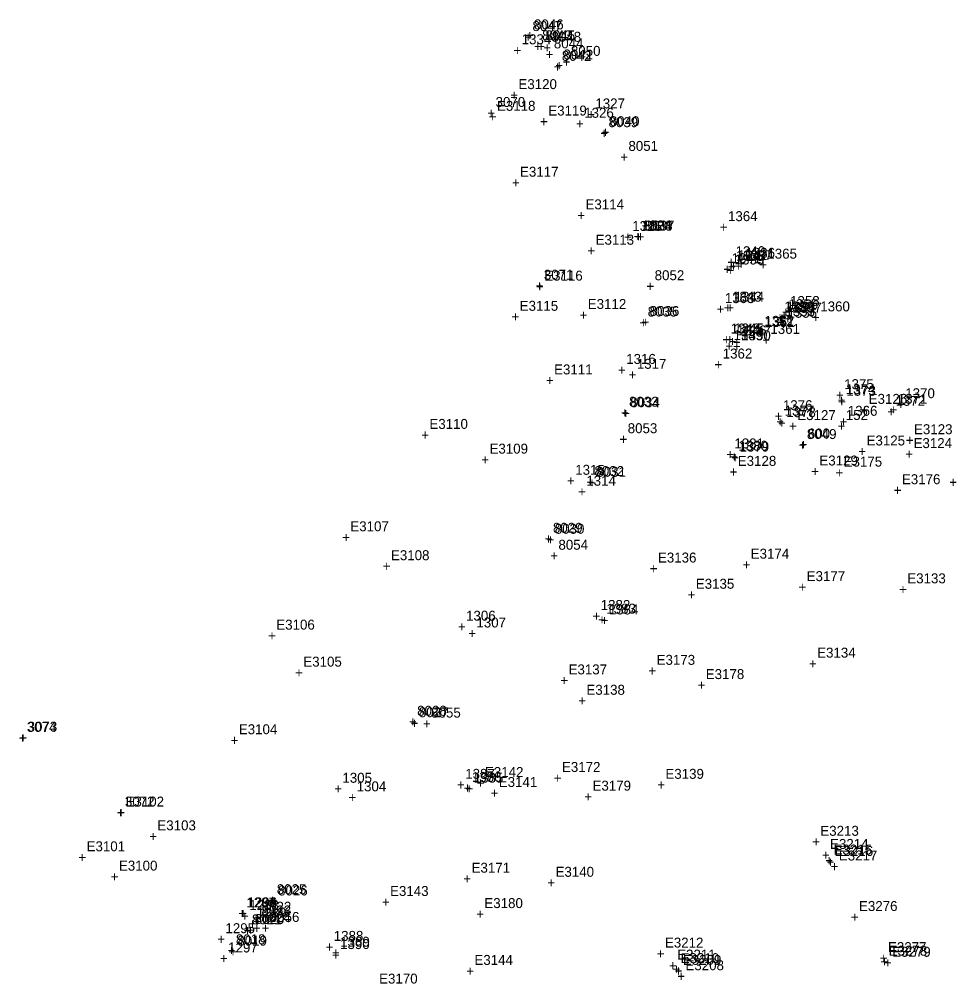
# Model space of a CAD drawing. Extents: x 1667192 to 1669644, y 336680 to 339991.
# Drawn here: x 1668101.3 to 1668335.8, y 339404.1 to 339646.3 of the extents above; entities that cross this region are included whole.
import ezdxf

# ---------------------------------------------------------------- set-up
doc = ezdxf.new("R2010")
doc.units = 0
for name, color, linetype in [('S_Control_BenchMark_Temp', 7, 'Continuous'), ('S_Control_Temp_Traverse', 7, 'Continuous'), ('S_Curb_Type_1', 7, 'Continuous'), ('S_Curb_Type_5', 7, 'Continuous'), ('S_Drainage_CB', 7, 'Continuous'), ('S_Drainage_Culvert_Top', 7, 'Continuous'), ('S_Drainage_Invert', 7, 'Continuous'), ('S_Fencing_ChainLink', 7, 'Continuous'), ('S_Fencing_Page', 7, 'Continuous'), ('S_Ground_Elevation', 7, 'Continuous'), ('S_Guardrail_Beam', 7, 'Continuous'), ('S_Roadway_Edge_Pavement', 7, 'Continuous'), ('S_Roadway_Edge_TW', 7, 'Continuous'), ('S_Traffic_Sign_SinglePost', 7, 'Continuous'), ('S_Utilities_Pole_Power', 7, 'Continuous')]:
    doc.layers.add(name, color=color, linetype=linetype)

msp = doc.modelspace()

# ---------------------------------------------------------------- texts
at = {"layer": 'S_Control_BenchMark_Temp'}
for s, p in [('8049', (1668299.17, 339540.9)), ('+', (1668297.11, 339538.15))]:
    msp.add_text(s, height=2.5, dxfattribs=at).set_placement(p)
at = {"layer": 'S_Control_Temp_Traverse'}
for s, p in [('152', (1668308.94, 339545.7)), ('+', (1668306.88, 339542.95)), ('600', (1668299.4, 339541.04)), ('600', (1668299.4, 339541.04)), ('600', (1668299.4, 339541.04)), ('600', (1668299.4, 339541.04)), ('+', (1668297.34, 339538.29)), ('+', (1668297.34, 339538.29)), ('+', (1668297.34, 339538.29)), ('+', (1668297.34, 339538.29))]:
    msp.add_text(s, height=2.5, dxfattribs=at).set_placement(p)
at = {"layer": 'S_Curb_Type_1'}
for s, p in [('8047', (1668230.24, 339643.36)), ('8043', (1668232.65, 339641.04)), ('+', (1668228.17, 339640.61)), ('+', (1668230.59, 339638.29)), ('8042', (1668237.62, 339635.88)), ('+', (1668235.56, 339633.13)), ('8039', (1668249.34, 339619.22)), ('+', (1668247.28, 339616.47)), ('8038', (1668257.99, 339593.25)), ('+', (1668255.93, 339590.5)), ('8035', (1668259.18, 339571.66)), ('+', (1668257.11, 339568.91)), ('1373', (1668309.06, 339551.77)), ('8033', (1668254.5, 339549.03)), ('+', (1668307, 339549.02)), ('1372', (1668321.43, 339549.25)), ('1378', (1668293.97, 339546.4)), ('+', (1668252.44, 339546.28)), ('+', (1668319.37, 339546.5)), ('+', (1668291.91, 339543.65)), ('1379', (1668282.24, 339537.76)), ('+', (1668280.18, 339535.01)), ('8032', (1668245.81, 339531.61)), ('+', (1668243.75, 339528.86)), ('8029', (1668235.37, 339517.35)), ('+', (1668233.31, 339514.6)), ('1384', (1668249.42, 339496.85)), ('+', (1668247.35, 339494.1)), ('8028', (1668201.27, 339471.41)), ('+', (1668199.21, 339468.66)), ('1385', (1668215.46, 339454.6)), ('+', (1668213.39, 339451.85)), ('E3215', (1668305.86, 339436.56)), ('+', (1668303.79, 339433.81)), ('8025', (1668166.01, 339426.6)), ('+', (1668163.94, 339423.85)), ('8022', (1668162.22, 339422.19)), ('8021', (1668159.77, 339419.02)), ('+', (1668160.16, 339419.44)), ('+', (1668157.71, 339416.27)), ('8018', (1668155.74, 339414.02)), ('+', (1668153.68, 339411.27)), ('1390', (1668181.91, 339412.82)), ('+', (1668179.85, 339410.07)), ('E3210', (1668267.47, 339409.28)), ('+', (1668265.41, 339406.53))]:
    msp.add_text(s, height=2.5, dxfattribs=at).set_placement(p)
at = {"layer": 'S_Curb_Type_5'}
for s, p in [('1338', (1668281.36, 339585.7)), ('1337', (1668283.03, 339585.83)), ('+', (1668279.3, 339582.95)), ('+', (1668280.97, 339583.08)), ('1339', (1668281.02, 339584.74)), ('+', (1668278.96, 339581.99)), ('1344', (1668280.99, 339575.38)), ('1354', (1668294.03, 339572.82)), ('1355', (1668294.55, 339573.52)), ('+', (1668278.93, 339572.63)), ('1353', (1668293.77, 339571.75)), ('1352', (1668288.51, 339569.33)), ('+', (1668291.7, 339569)), ('+', (1668291.97, 339570.07)), ('+', (1668292.49, 339570.77)), ('1345', (1668280.91, 339567.42)), ('1346', (1668281.59, 339566.94)), ('1347', (1668282.63, 339566.73)), ('+', (1668286.44, 339566.58)), ('+', (1668278.85, 339564.67)), ('+', (1668279.53, 339564.19)), ('+', (1668280.57, 339563.98)), ('E3279', (1668320.59, 339410.88)), ('+', (1668318.53, 339408.13))]:
    msp.add_text(s, height=2.5, dxfattribs=at).set_placement(p)
at = {"layer": 'S_Drainage_CB'}
for s, p in [('8048', (1668235.02, 339640.67)), ('+', (1668232.96, 339637.92)), ('8024', (1668162.1, 339419.57)), ('+', (1668160.04, 339416.82))]:
    msp.add_text(s, height=2.5, dxfattribs=at).set_placement(p)
at = {"layer": 'S_Drainage_Culvert_Top'}
for s, p in [('1288', (1668159.07, 339422.61)), ('1289', (1668160.97, 339420.71)), ('+', (1668157.01, 339419.86)), ('+', (1668158.91, 339417.96))]:
    msp.add_text(s, height=2.5, dxfattribs=at).set_placement(p)
at = {"layer": 'S_Drainage_Invert'}
for s, p in [('1287', (1668158.39, 339423.26)), ('+', (1668156.33, 339420.51))]:
    msp.add_text(s, height=2.5, dxfattribs=at).set_placement(p)
at = {"layer": 'S_Fencing_ChainLink'}
for s, p in [('3070', (1668220.97, 339624.29)), ('+', (1668218.91, 339621.54)), ('3071', (1668233.09, 339580.91)), ('+', (1668231.03, 339578.16)), ('3073', (1668103.42, 339467.43)), ('+', (1668101.36, 339464.68)), ('3072', (1668127.86, 339448.6)), ('+', (1668125.8, 339445.85))]:
    msp.add_text(s, height=2.5, dxfattribs=at).set_placement(p)
at = {"layer": 'S_Fencing_Page'}
for s, p in [('3074', (1668103.23, 339467.35)), ('+', (1668101.16, 339464.6))]:
    msp.add_text(s, height=2.5, dxfattribs=at).set_placement(p)
at = {"layer": 'S_Ground_Elevation'}
for s, p in [('1334', (1668227.52, 339640.05)), ('+', (1668225.46, 339637.3)), ('E3120', (1668226.71, 339628.78)), ('+', (1668224.65, 339626.03)), ('1327', (1668246.03, 339623.93)), ('E3118', (1668221.32, 339623.33)), ('E3119', (1668234.21, 339622.15)), ('1326', (1668243.23, 339621.58)), ('+', (1668219.26, 339620.58)), ('+', (1668232.15, 339619.4)), ('+', (1668243.97, 339621.18)), ('+', (1668241.17, 339618.83)), ('E3117', (1668227.12, 339606.78)), ('+', (1668225.06, 339604.03)), ('E3114', (1668243.56, 339598.59)), ('+', (1668241.5, 339595.84)), ('1325', (1668255.3, 339593.16)), ('1324', (1668257.75, 339593.29)), ('+', (1668253.24, 339590.41)), ('+', (1668255.69, 339590.54)), ('E3113', (1668246.1, 339589.7)), ('+', (1668244.04, 339586.95)), ('E3116', (1668233.19, 339580.69)), ('+', (1668231.13, 339577.94)), ('E3115', (1668227.03, 339573.11)), ('E3112', (1668244.13, 339573.57)), ('+', (1668242.07, 339570.82)), ('+', (1668224.97, 339570.36)), ('1316', (1668253.78, 339559.77)), ('1317', (1668256.45, 339558.54)), ('E3111', (1668235.67, 339557.13)), ('+', (1668251.72, 339557.02)), ('+', (1668233.61, 339554.38)), ('+', (1668254.39, 339555.79)), ('E3126', (1668314.7, 339549.74)), ('+', (1668312.64, 339546.99)), ('E3127', (1668296.76, 339545.66)), ('E3110', (1668204.35, 339543.45)), ('+', (1668294.69, 339542.91)), ('E3123', (1668326.08, 339542.12)), ('+', (1668202.29, 339540.7)), ('+', (1668324.02, 339539.37)), ('E3109', (1668219.45, 339537.24)), ('+', (1668217.39, 339534.49)), ('E3128', (1668281.81, 339534.17)), ('1315', (1668240.98, 339531.92)), ('E3175', (1668308.41, 339533.98)), ('+', (1668279.75, 339531.42)), ('+', (1668306.34, 339531.23)), ('E3176', (1668323.04, 339529.56)), ('+', (1668238.92, 339529.17)), ('1314', (1668243.76, 339529.18)), ('+', (1668334.92, 339528.82)), ('+', (1668241.7, 339526.43)), ('+', (1668320.98, 339526.81)), ('E3107', (1668184.49, 339517.74)), ('+', (1668182.43, 339514.99)), ('E3108', (1668194.7, 339510.48)), ('E3136', (1668261.76, 339509.89)), ('E3174', (1668285.06, 339510.86)), ('+', (1668283, 339508.11)), ('+', (1668192.64, 339507.73)), ('+', (1668259.7, 339507.14)), ('E3177', (1668299.12, 339505.22)), ('E3133', (1668324.39, 339504.67)), ('+', (1668297.05, 339502.47)), ('+', (1668322.33, 339501.92)), ('E3106', (1668165.89, 339493.04)), ('1306', (1668213.56, 339495.28)), ('1307', (1668216.15, 339493.58)), ('+', (1668211.5, 339492.53)), ('+', (1668163.83, 339490.29)), ('+', (1668214.09, 339490.83)), ('E3134', (1668301.75, 339486.01)), ('E3105', (1668172.68, 339483.75)), ('E3173', (1668261.42, 339484.2)), ('E3137', (1668239.31, 339481.8)), ('+', (1668259.36, 339481.45)), ('+', (1668299.69, 339483.26)), ('+', (1668170.61, 339481)), ('+', (1668237.25, 339479.05)), ('E3178', (1668273.77, 339480.62)), ('+', (1668271.71, 339477.87)), ('E3104', (1668156.48, 339466.77)), ('+', (1668154.42, 339464.02)), ('E3172', (1668237.65, 339457.3)), ('1305', (1668182.49, 339454.58)), ('E3142', (1668218.3, 339456.03)), ('E3139', (1668263.63, 339455.57)), ('1304', (1668186.07, 339452.43)), ('+', (1668216.24, 339453.28)), ('+', (1668235.59, 339454.55)), ('E3179', (1668245.32, 339452.6)), ('+', (1668261.57, 339452.82)), ('+', (1668180.43, 339451.83)), ('+', (1668243.26, 339449.85)), ('E3102', (1668128.02, 339448.61)), ('+', (1668184.01, 339449.68)), ('+', (1668125.96, 339445.86)), ('E3103', (1668136.02, 339442.64)), ('E3213', (1668302.55, 339441.26)), ('E3101', (1668118.24, 339437.38)), ('+', (1668133.96, 339439.89)), ('+', (1668300.49, 339438.51)), ('E3214', (1668304.99, 339437.97)), ('+', (1668302.93, 339435.22)), ('+', (1668116.18, 339434.63)), ('E3100', (1668126.36, 339432.52)), ('E3171', (1668214.94, 339431.99)), ('E3140', (1668236.03, 339430.97)), ('+', (1668124.3, 339429.77)), ('+', (1668212.88, 339429.24)), ('+', (1668233.97, 339428.22)), ('E3143', (1668194.47, 339426.15)), ('1296', (1668158.64, 339423.3)), ('+', (1668192.41, 339423.4)), ('E3180', (1668218.16, 339423.11)), ('+', (1668156.58, 339420.55)), ('+', (1668216.1, 339420.36)), ('1295', (1668153.11, 339416.81)), ('+', (1668151.04, 339414.06)), ('E3212', (1668263.51, 339413.19)), ('1297', (1668153.79, 339411.97)), ('+', (1668151.73, 339409.22)), ('E3144', (1668215.66, 339408.84)), ('+', (1668261.45, 339410.44)), ('E3211', (1668266.59, 339410.18)), ('+', (1668264.53, 339407.43)), ('E3170', (1668191.72, 339404.15)), ('+', (1668213.6, 339406.09))]:
    msp.add_text(s, height=2.5, dxfattribs=at).set_placement(p)
at = {"layer": 'S_Guardrail_Beam'}
for s, p in [('E3125', (1668314.16, 339539.29)), ('E3124', (1668325.96, 339538.63)), ('E3129', (1668302.31, 339534.26)), ('+', (1668312.1, 339536.54)), ('+', (1668323.9, 339535.88)), ('+', (1668300.24, 339531.51)), ('E3135', (1668271.27, 339503.3)), ('+', (1668269.21, 339500.55)), ('E3138', (1668243.79, 339476.68)), ('+', (1668241.73, 339473.93)), ('E3141', (1668221.77, 339453.52)), ('+', (1668219.7, 339450.77))]:
    msp.add_text(s, height=2.5, dxfattribs=at).set_placement(p)
at = {"layer": 'S_Roadway_Edge_Pavement'}
for s, p in [('8046', (1668230.63, 339643.78)), ('8045', (1668233.52, 339641.02)), ('+', (1668228.57, 339641.03)), ('8044', (1668235.61, 339639.01)), ('+', (1668231.46, 339638.27)), ('+', (1668233.55, 339636.26)), ('8041', (1668238.02, 339636.22)), ('+', (1668235.96, 339633.47)), ('8040', (1668249.67, 339619.47)), ('+', (1668247.61, 339616.72)), ('8037', (1668258.46, 339593.26)), ('+', (1668256.4, 339590.51)), ('1341', (1668280.25, 339585.06)), ('1340', (1668281.26, 339586.82)), ('1336', (1668283.73, 339586.41)), ('+', (1668279.2, 339584.07)), ('+', (1668281.67, 339583.66)), ('+', (1668278.19, 339582.31)), ('1343', (1668280.36, 339575.4)), ('1358', (1668294.95, 339574.31)), ('8036', (1668259.67, 339571.81)), ('+', (1668278.3, 339572.65)), ('+', (1668292.89, 339571.56)), ('1356', (1668294.28, 339571.36)), ('1357', (1668295.46, 339572.66)), ('+', (1668257.61, 339569.06)), ('1351', (1668288.63, 339569.05)), ('+', (1668292.22, 339568.61)), ('+', (1668293.4, 339569.91)), ('1348', (1668280.02, 339567.4)), ('1349', (1668280.75, 339565.75)), ('1350', (1668282.65, 339565.69)), ('+', (1668286.57, 339566.3)), ('+', (1668277.96, 339564.65)), ('+', (1668278.69, 339563)), ('+', (1668280.59, 339562.94)), ('1374', (1668308.93, 339552.18)), ('8034', (1668254.8, 339548.88)), ('+', (1668306.87, 339549.43)), ('1371', (1668321.98, 339549.75)), ('1377', (1668293.56, 339546.78)), ('+', (1668319.91, 339547)), ('+', (1668252.74, 339546.13)), ('+', (1668291.5, 339544.03)), ('1380', (1668281.95, 339537.98)), ('+', (1668279.89, 339535.23)), ('8031', (1668246.27, 339531.42)), ('+', (1668244.21, 339528.67)), ('8030', (1668235.84, 339517.11)), ('+', (1668233.78, 339514.36)), ('1383', (1668248.78, 339497.06)), ('+', (1668246.72, 339494.31)), ('8027', (1668201.69, 339471.05)), ('+', (1668199.63, 339468.3)), ('1386', (1668215.01, 339454.8)), ('+', (1668212.95, 339452.05)), ('E3216', (1668306.16, 339436.19)), ('+', (1668304.1, 339433.44)), ('8026', (1668166.33, 339426.28)), ('+', (1668164.27, 339423.53)), ('8023', (1668162.17, 339421.25)), ('+', (1668160.11, 339418.5)), ('8020', (1668160.48, 339419.11)), ('+', (1668158.42, 339416.36)), ('8019', (1668156.1, 339413.67)), ('1389', (1668181.94, 339413.41)), ('E3278', (1668319.72, 339411.16)), ('+', (1668154.04, 339410.92)), ('+', (1668179.88, 339410.66)), ('E3209', (1668268.01, 339408.85)), ('+', (1668317.66, 339408.41)), ('+', (1668265.95, 339406.1))]:
    msp.add_text(s, height=2.5, dxfattribs=at).set_placement(p)
at = {"layer": 'S_Roadway_Edge_TW'}
for s, p in [('8050', (1668239.89, 339637.13)), ('+', (1668237.83, 339634.38)), ('8051', (1668254.34, 339613.26)), ('+', (1668252.28, 339610.51)), ('1364', (1668279.35, 339595.62)), ('+', (1668277.29, 339592.87)), ('1365', (1668289.24, 339586.2)), ('+', (1668287.18, 339583.45)), ('8052', (1668260.93, 339580.79)), ('+', (1668258.86, 339578.04)), ('1363', (1668278.56, 339575.04)), ('1360', (1668302.53, 339572.96)), ('+', (1668276.5, 339572.29)), ('+', (1668300.46, 339570.21)), ('1361', (1668290, 339567.31)), ('+', (1668287.94, 339564.56)), ('1362', (1668278.02, 339561.12)), ('+', (1668275.95, 339558.37)), ('1375', (1668308.53, 339553.43)), ('1370', (1668323.88, 339551.15)), ('+', (1668306.47, 339550.68)), ('1376', (1668293.14, 339548.15)), ('+', (1668321.82, 339548.4)), ('+', (1668291.08, 339545.4)), ('8053', (1668254.16, 339542.37)), ('+', (1668252.1, 339539.62)), ('1381', (1668280.96, 339538.55)), ('+', (1668278.9, 339535.8)), ('8054', (1668236.76, 339513.1)), ('+', (1668234.7, 339510.35)), ('1382', (1668247.38, 339497.98)), ('+', (1668245.31, 339495.23)), ('8055', (1668204.79, 339470.94)), ('+', (1668202.73, 339468.19)), ('1387', (1668213.35, 339455.57)), ('+', (1668211.29, 339452.82)), ('E3217', (1668307.19, 339435.06)), ('+', (1668305.13, 339432.31)), ('E3276', (1668312.26, 339422.37)), ('8056', (1668164.25, 339419.63)), ('+', (1668310.2, 339419.62)), ('+', (1668162.19, 339416.88)), ('1388', (1668180.32, 339414.87)), ('+', (1668178.26, 339412.12)), ('E3277', (1668319.54, 339412.05)), ('+', (1668317.48, 339409.3)), ('E3208', (1668268.67, 339407.51)), ('+', (1668266.61, 339404.76))]:
    msp.add_text(s, height=2.5, dxfattribs=at).set_placement(p)
at = {"layer": 'S_Traffic_Sign_SinglePost'}
for s, p in [('1342', (1668281.82, 339585.83)), ('+', (1668279.76, 339583.08)), ('1359', (1668293.51, 339572.93)), ('+', (1668291.44, 339570.18))]:
    msp.add_text(s, height=2.5, dxfattribs=at).set_placement(p)
at = {"layer": 'S_Utilities_Pole_Power'}
for s, p in [('1366', (1668309.45, 339546.74)), ('+', (1668307.39, 339543.99))]:
    msp.add_text(s, height=2.5, dxfattribs=at).set_placement(p)

doc.saveas('drawing.dxf')
